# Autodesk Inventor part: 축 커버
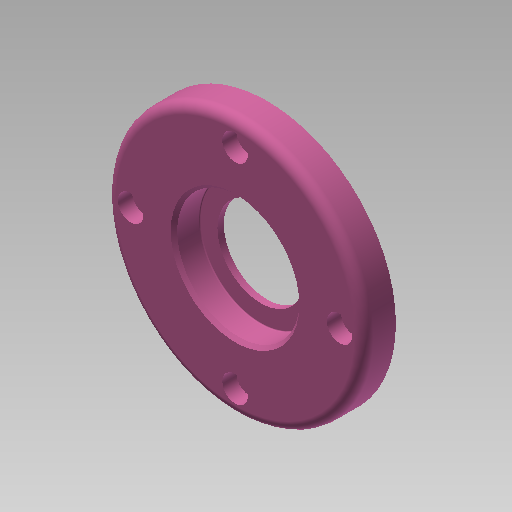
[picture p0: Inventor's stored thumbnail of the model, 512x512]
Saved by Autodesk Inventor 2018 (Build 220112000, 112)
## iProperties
Created: 2015-10
Part Number: 축 커버
Document SubType Name: Modeling
Designer: mdu
Density: 1 g/cm^3
Material: 강철, 연강
Appearance: 분홍색
Author: mdu
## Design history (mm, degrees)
sketch "스케치1"
  geometry: C1 r 40 at (0, 0) reference; C2 r 26 at (0, 0) reference; 1 further point
  node "참조1"
  node "참조2"
extrude "돌출1" new body sketch "스케치1" distance "d0" = 10; taper "d1" = 0 deg
extrude "돌출2" join sketch "스케치1" distance "d2" = 3; taper "d3" = 0 deg
hole "구멍1" diameter "d6" = 27; stored, may be unused: countersink angle "d10" = 90 deg, drill point angle "d12" = 118 deg; dims "d4" = 10, "d5" = 10, "d7" = 6, "d8" = 38, "d9" = 8, "d11" = 8
sketch "스케치2"
  geometry: C1 r 20 at (0, 0); 1 further point
  constraints: 1 centre point, 1 coincident
  dimensions: "d13" = 40 diameter of C1
extrude "돌출3" cut sketch "스케치2" distance "d14" = 3; taper "d15" = 0 deg
sketch "스케치3"
  geometry: C1 r 1.621 at (0, 32.5) reference; 1 further point
hole "구멍2" sketch "스케치3" at (0, 32.5) diameter "d16" = 4.5; stored, may be unused: countersink angle "d20" = 90 deg, drill point angle "d22" = 118 deg; dims "d17" = 6, "d18" = 8, "d19" = 4.4, "d21" = 8
fillet "모깎기1" dims "d26" = 3, "d27" = 0.3
chamfer "모따기1" distance "d28" = 1; stored, may be unused: second distance "d29" = 2, angle "d30" = 45 deg
node "솔리드1"
pattern_circular "원형 패턴1" dims angle "d24" = 360 deg
node "참조3"
